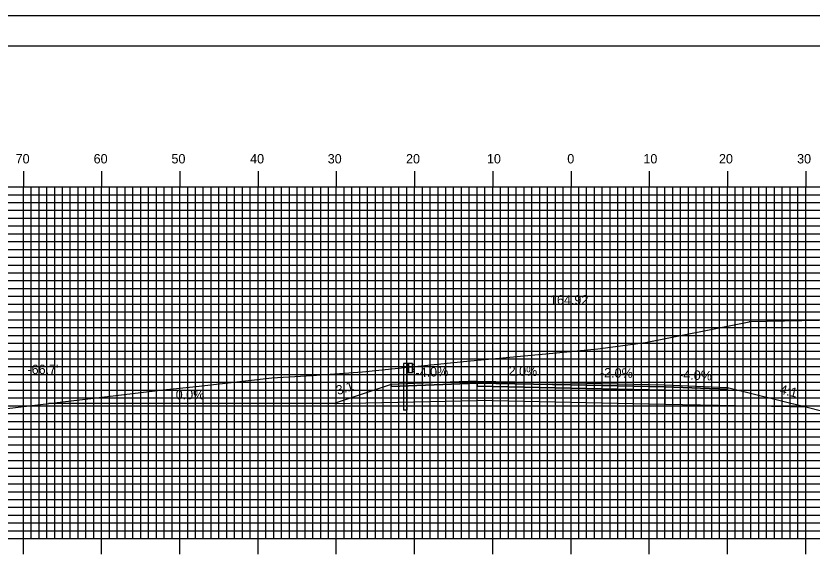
# Model space of a CAD drawing. Extents: x 1793666 to 1794009, y 442591 to 442811.
# Drawn here: x 1793760.4 to 1793862.1, y 442741.2 to 442810.5 of the extents above; entities that cross this region are included whole.
import ezdxf

# ---------------------------------------------------------------- set-up
doc = ezdxf.new("R2010")
doc.units = 0
for name, color, linetype in [('ANNOTATION', 7, 'Continuous'), ('BORDER', 7, 'Continuous'), ('D_Guardrail_Beam_Lt', 7, 'Continuous'), ('D_Roadway_Centerline', 7, 'Continuous'), ('D_Roadway_Centerline_Text', 7, 'Continuous'), ('D_Roadway_Edge_Shoulder', 7, 'Continuous'), ('D_Roadway_Edge_TW', 7, 'Continuous'), ('D_Roadway_FinishedGrade', 7, 'Continuous'), ('D_Roadway_Pavement', 7, 'Continuous'), ('D_Roadway_SlopeLines', 7, 'Continuous'), ('D_Roadway_SubGrade', 7, 'Continuous'), ('D_Text_Standard', 7, 'Continuous'), ('H_V ANNOTATION', 7, 'Continuous'), ('MAJOR', 7, 'Continuous'), ('MINOR', 7, 'Continuous'), ('PLOT BOUNDARY', 7, 'Continuous'), ('S_Roadway_Centerline', 7, 'Continuous')]:
    doc.layers.add(name, color=color, linetype=linetype)

msp = doc.modelspace()

# ---------------------------------------------------------------- linework, layer by layer
at = {"layer": 'BORDER'}
msp.add_lwpolyline([(1793681.71, 442596.67), (1794001.71, 442596.67), (1794001.71, 442806.67), (1793681.71, 442806.67)], close=True, dxfattribs=at)
at = {"layer": 'D_Guardrail_Beam_Lt'}
for p, q in [((1793809.88, 442766.09), (1793809.88, 442760.09)), ((1793810.36, 442766.09), (1793809.88, 442766.09)), ((1793811.04, 442766.09), (1793810.36, 442766.09)), ((1793810.36, 442766.09), (1793810.36, 442764.92)), ((1793810.42, 442766.09), (1793810.42, 442764.92)), ((1793810.52, 442766.09), (1793810.52, 442764.92)), ((1793811.04, 442764.92), (1793811.04, 442766.09)), ((1793811.04, 442766), (1793811.12, 442765.99)), ((1793811.13, 442765.98), (1793811.28, 442765.88)), ((1793810.36, 442764.92), (1793811.04, 442764.92)), ((1793810.38, 442760.09), (1793810.38, 442764.92)), ((1793811.12, 442765.02), (1793811.04, 442765)), ((1793811.05, 442765.54), (1793811.05, 442765.47)), ((1793811.28, 442765.74), (1793811.08, 442765.6)), ((1793811.08, 442765.4), (1793811.28, 442765.27)), ((1793811.28, 442765.12), (1793811.13, 442765.02)), ((1793810.38, 442760.09), (1793809.88, 442760.09))]:
    msp.add_line(p, q, dxfattribs=at)
for centre, major_axis, start_param, end_param in [((1793811.11, 442765.95), (0.0417, 0), 0.959931, 1.376053), ((1793811.13, 442765.54), (-0.0789, 0), 5.323254, 6.283185), ((1793811.13, 442765.47), (-0.0789, 0), 6.283185, 7.243116), ((1793811.11, 442765.06), (0.0417, 0), 4.907132, 5.323254), ((1793811.23, 442765.81), (0.0877, 0), 5.323254, 7.243116), ((1793811.23, 442765.2), (0.0877, 0), 5.323254, 7.243116)]:
    msp.add_ellipse(centre, major_axis=major_axis, ratio=0.995501, start_param=start_param, end_param=end_param, dxfattribs=at)
at = {"layer": 'D_Roadway_Edge_Shoulder'}
for points in [[(1793819.31, 442763.82), (1793811.31, 442763.5), (1793811.31, 442763.5), (1793808.31, 442763.38), (1793808.31, 442763.13), (1793819.31, 442763.57)], [(1793843.31, 442763.34), (1793851.31, 442763.02), (1793851.31, 442762.77), (1793843.31, 442763.09)]]:
    msp.add_lwpolyline(points, close=True, dxfattribs=at)
at = {"layer": 'D_Roadway_Edge_TW'}
msp.add_lwpolyline([(1793819.31, 442763.57), (1793819.31, 442763.82), (1793831.31, 442763.58), (1793843.31, 442763.34), (1793843.31, 442763.09), (1793831.31, 442763.33)], close=True, dxfattribs=at)
at = {"layer": 'D_Roadway_FinishedGrade'}
msp.add_line((1793801.04, 442760.96), (1793764.5, 442760.96), dxfattribs=at)
at = {"layer": 'D_Roadway_Pavement'}
for points in [[(1793819.31, 442763.57), (1793819.31, 442763.16)], [(1793819.31, 442763.57), (1793819.31, 442763.16)], [(1793843.31, 442763.09), (1793843.31, 442762.68)]]:
    msp.add_lwpolyline(points, dxfattribs=at)
msp.add_lwpolyline([(1793819.31, 442763.16), (1793819.31, 442763.57), (1793831.31, 442763.33), (1793843.31, 442763.09), (1793843.31, 442762.68), (1793831.31, 442762.92)], close=True, dxfattribs=at)
at = {"layer": 'D_Roadway_SlopeLines'}
msp.add_line((1793808.31, 442763.38), (1793801.04, 442760.96), dxfattribs=at)
msp.add_lwpolyline([(1793851.31, 442763.02), (1793861.32, 442760.52)], dxfattribs=at)
at = {"layer": 'D_Roadway_SubGrade'}
msp.add_line((1793861.49, 442760.48), (1793863.31, 442760.02), dxfattribs=at)
for points in [[(1793819.31, 442763.16), (1793819.31, 442763.57), (1793808.31, 442763.13), (1793808.31, 442763.38), (1793801.04, 442760.96), (1793819.31, 442761.32)], [(1793819.31, 442761.32), (1793819.31, 442763.57), (1793819.31, 442763.16), (1793831.31, 442762.92), (1793843.31, 442762.68), (1793843.31, 442763.09), (1793843.31, 442760.84), (1793831.31, 442761.08)], [(1793843.31, 442762.68), (1793843.31, 442763.09), (1793851.31, 442762.77), (1793851.31, 442763.02), (1793861.49, 442760.48), (1793843.31, 442760.84)]]:
    msp.add_lwpolyline(points, close=True, dxfattribs=at)
at = {"layer": 'MAJOR'}
for p, q in [((1793761.31, 442790.67), (1793761.31, 442788.67)), ((1793771.31, 442790.67), (1793771.31, 442788.67)), ((1793781.31, 442790.67), (1793781.31, 442788.67)), ((1793791.31, 442790.67), (1793791.31, 442788.67)), ((1793801.31, 442790.67), (1793801.31, 442788.67)), ((1793811.31, 442790.67), (1793811.31, 442788.67)), ((1793821.31, 442790.67), (1793821.31, 442788.67)), ((1793831.31, 442790.67), (1793831.31, 442788.67)), ((1793841.31, 442790.67), (1793841.31, 442788.67)), ((1793851.31, 442790.67), (1793851.31, 442788.67)), ((1793861.31, 442790.67), (1793861.31, 442788.67)), ((1793691.31, 442788.67), (1793971.31, 442788.67)), ((1793691.31, 442788.67), (1793971.31, 442788.67)), ((1793761.31, 442743.67), (1793761.31, 442788.67)), ((1793771.31, 442743.67), (1793771.31, 442788.67)), ((1793781.31, 442743.67), (1793781.31, 442788.67)), ((1793791.31, 442743.67), (1793791.31, 442788.67)), ((1793801.31, 442743.67), (1793801.31, 442788.67)), ((1793811.31, 442743.67), (1793811.31, 442788.67)), ((1793821.31, 442743.67), (1793821.31, 442788.67)), ((1793831.31, 442743.67), (1793831.31, 442788.67)), ((1793841.31, 442743.67), (1793841.31, 442788.67)), ((1793851.31, 442743.67), (1793851.31, 442788.67)), ((1793861.31, 442743.67), (1793861.31, 442788.67)), ((1793691.31, 442783.67), (1793971.31, 442783.67)), ((1793691.31, 442778.67), (1793971.31, 442778.67)), ((1793691.31, 442773.67), (1793971.31, 442773.67)), ((1793691.31, 442768.67), (1793971.31, 442768.67)), ((1793691.31, 442763.67), (1793971.31, 442763.67)), ((1793691.31, 442758.67), (1793971.31, 442758.67)), ((1793691.31, 442753.67), (1793971.31, 442753.67)), ((1793691.31, 442748.67), (1793971.31, 442748.67)), ((1793691.31, 442743.67), (1793971.31, 442743.67)), ((1793691.31, 442743.67), (1793971.31, 442743.67)), ((1793761.31, 442741.66), (1793761.31, 442743.67)), ((1793771.31, 442741.66), (1793771.31, 442743.67)), ((1793781.31, 442741.66), (1793781.31, 442743.67)), ((1793791.31, 442741.66), (1793791.31, 442743.67)), ((1793801.31, 442741.66), (1793801.31, 442743.67)), ((1793811.31, 442741.66), (1793811.31, 442743.67)), ((1793821.31, 442741.66), (1793821.31, 442743.67)), ((1793831.31, 442741.66), (1793831.31, 442743.67)), ((1793841.31, 442741.66), (1793841.31, 442743.67)), ((1793851.31, 442741.66), (1793851.31, 442743.67)), ((1793861.31, 442741.66), (1793861.31, 442743.67))]:
    msp.add_line(p, q, dxfattribs=at)
at = {"layer": 'MINOR'}
for p, q in [((1793762.31, 442743.67), (1793762.31, 442788.67)), ((1793763.31, 442743.67), (1793763.31, 442788.67)), ((1793764.31, 442743.67), (1793764.31, 442788.67)), ((1793765.31, 442743.67), (1793765.31, 442788.67)), ((1793766.31, 442743.67), (1793766.31, 442788.67)), ((1793767.31, 442743.67), (1793767.31, 442788.67)), ((1793768.31, 442743.67), (1793768.31, 442788.67)), ((1793769.31, 442743.67), (1793769.31, 442788.67)), ((1793770.31, 442743.67), (1793770.31, 442788.67)), ((1793772.31, 442743.67), (1793772.31, 442788.67)), ((1793773.31, 442743.67), (1793773.31, 442788.67)), ((1793774.31, 442743.67), (1793774.31, 442788.67)), ((1793775.31, 442743.67), (1793775.31, 442788.67)), ((1793776.31, 442743.67), (1793776.31, 442788.67)), ((1793777.31, 442743.67), (1793777.31, 442788.67)), ((1793778.31, 442743.67), (1793778.31, 442788.67)), ((1793779.31, 442743.67), (1793779.31, 442788.67)), ((1793780.31, 442743.67), (1793780.31, 442788.67)), ((1793782.31, 442743.67), (1793782.31, 442788.67)), ((1793783.31, 442743.67), (1793783.31, 442788.67)), ((1793784.31, 442743.67), (1793784.31, 442788.67)), ((1793785.31, 442743.67), (1793785.31, 442788.67)), ((1793786.31, 442743.67), (1793786.31, 442788.67)), ((1793787.31, 442743.67), (1793787.31, 442788.67)), ((1793788.31, 442743.67), (1793788.31, 442788.67)), ((1793789.31, 442743.67), (1793789.31, 442788.67)), ((1793790.31, 442743.67), (1793790.31, 442788.67)), ((1793792.31, 442743.67), (1793792.31, 442788.67)), ((1793793.31, 442743.67), (1793793.31, 442788.67)), ((1793794.31, 442743.67), (1793794.31, 442788.67)), ((1793795.31, 442743.67), (1793795.31, 442788.67)), ((1793796.31, 442743.67), (1793796.31, 442788.67)), ((1793797.31, 442743.67), (1793797.31, 442788.67)), ((1793798.31, 442743.67), (1793798.31, 442788.67)), ((1793799.31, 442743.67), (1793799.31, 442788.67)), ((1793800.31, 442743.67), (1793800.31, 442788.67)), ((1793802.31, 442743.67), (1793802.31, 442788.67)), ((1793803.31, 442743.67), (1793803.31, 442788.67)), ((1793804.31, 442743.67), (1793804.31, 442788.67)), ((1793805.31, 442743.67), (1793805.31, 442788.67)), ((1793806.31, 442743.67), (1793806.31, 442788.67)), ((1793807.31, 442743.67), (1793807.31, 442788.67)), ((1793808.31, 442743.67), (1793808.31, 442788.67)), ((1793809.31, 442743.67), (1793809.31, 442788.67)), ((1793810.31, 442743.67), (1793810.31, 442788.67)), ((1793812.31, 442743.67), (1793812.31, 442788.67)), ((1793813.31, 442743.67), (1793813.31, 442788.67)), ((1793814.31, 442743.67), (1793814.31, 442788.67)), ((1793815.31, 442743.67), (1793815.31, 442788.67)), ((1793816.31, 442743.67), (1793816.31, 442788.67)), ((1793817.31, 442743.67), (1793817.31, 442788.67)), ((1793818.31, 442743.67), (1793818.31, 442788.67)), ((1793819.31, 442743.67), (1793819.31, 442788.67)), ((1793820.31, 442743.67), (1793820.31, 442788.67)), ((1793822.31, 442743.67), (1793822.31, 442788.67)), ((1793823.31, 442743.67), (1793823.31, 442788.67)), ((1793824.31, 442743.67), (1793824.31, 442788.67)), ((1793825.31, 442743.67), (1793825.31, 442788.67)), ((1793826.31, 442743.67), (1793826.31, 442788.67)), ((1793827.31, 442743.67), (1793827.31, 442788.67)), ((1793828.31, 442743.67), (1793828.31, 442788.67)), ((1793829.31, 442743.67), (1793829.31, 442788.67)), ((1793830.31, 442743.67), (1793830.31, 442788.67)), ((1793832.31, 442743.67), (1793832.31, 442788.67)), ((1793833.31, 442743.67), (1793833.31, 442788.67)), ((1793834.31, 442743.67), (1793834.31, 442788.67)), ((1793835.31, 442743.67), (1793835.31, 442788.67)), ((1793836.31, 442743.67), (1793836.31, 442788.67)), ((1793837.31, 442743.67), (1793837.31, 442788.67)), ((1793838.31, 442743.67), (1793838.31, 442788.67)), ((1793839.31, 442743.67), (1793839.31, 442788.67)), ((1793840.31, 442743.67), (1793840.31, 442788.67)), ((1793842.31, 442743.67), (1793842.31, 442788.67)), ((1793843.31, 442743.67), (1793843.31, 442788.67)), ((1793844.31, 442743.67), (1793844.31, 442788.67)), ((1793845.31, 442743.67), (1793845.31, 442788.67)), ((1793846.31, 442743.67), (1793846.31, 442788.67)), ((1793847.31, 442743.67), (1793847.31, 442788.67)), ((1793848.31, 442743.67), (1793848.31, 442788.67)), ((1793849.31, 442743.67), (1793849.31, 442788.67)), ((1793850.31, 442743.67), (1793850.31, 442788.67)), ((1793852.31, 442743.67), (1793852.31, 442788.67)), ((1793853.31, 442743.67), (1793853.31, 442788.67)), ((1793854.31, 442743.67), (1793854.31, 442788.67)), ((1793855.31, 442743.67), (1793855.31, 442788.67)), ((1793856.31, 442743.67), (1793856.31, 442788.67)), ((1793857.31, 442743.67), (1793857.31, 442788.67)), ((1793858.31, 442743.67), (1793858.31, 442788.67)), ((1793859.31, 442743.67), (1793859.31, 442788.67)), ((1793860.31, 442743.67), (1793860.31, 442788.67)), ((1793691.31, 442787.67), (1793971.31, 442787.67)), ((1793691.31, 442786.67), (1793971.31, 442786.67)), ((1793691.31, 442785.67), (1793971.31, 442785.67)), ((1793691.31, 442784.67), (1793971.31, 442784.67)), ((1793691.31, 442782.67), (1793971.31, 442782.67)), ((1793691.31, 442781.67), (1793971.31, 442781.67)), ((1793691.31, 442780.67), (1793971.31, 442780.67)), ((1793691.31, 442779.67), (1793971.31, 442779.67)), ((1793691.31, 442777.67), (1793971.31, 442777.67)), ((1793691.31, 442776.67), (1793971.31, 442776.67)), ((1793691.31, 442775.67), (1793971.31, 442775.67)), ((1793691.31, 442774.67), (1793971.31, 442774.67)), ((1793691.31, 442772.67), (1793971.31, 442772.67)), ((1793691.31, 442771.67), (1793971.31, 442771.67)), ((1793691.31, 442770.67), (1793971.31, 442770.67)), ((1793691.31, 442769.67), (1793971.31, 442769.67)), ((1793691.31, 442767.67), (1793971.31, 442767.67)), ((1793691.31, 442766.67), (1793971.31, 442766.67)), ((1793691.31, 442765.67), (1793971.31, 442765.67)), ((1793691.31, 442764.67), (1793971.31, 442764.67)), ((1793691.31, 442762.67), (1793971.31, 442762.67)), ((1793691.31, 442761.67), (1793971.31, 442761.67)), ((1793691.31, 442760.67), (1793971.31, 442760.67)), ((1793691.31, 442759.67), (1793971.31, 442759.67)), ((1793691.31, 442757.67), (1793971.31, 442757.67)), ((1793691.31, 442756.67), (1793971.31, 442756.67)), ((1793691.31, 442755.67), (1793971.31, 442755.67)), ((1793691.31, 442754.67), (1793971.31, 442754.67)), ((1793691.31, 442752.67), (1793971.31, 442752.67)), ((1793691.31, 442751.67), (1793971.31, 442751.67)), ((1793691.31, 442750.67), (1793971.31, 442750.67)), ((1793691.31, 442749.67), (1793971.31, 442749.67)), ((1793691.31, 442747.67), (1793971.31, 442747.67)), ((1793691.31, 442746.67), (1793971.31, 442746.67)), ((1793691.31, 442745.67), (1793971.31, 442745.67)), ((1793691.31, 442744.67), (1793971.31, 442744.67))]:
    msp.add_line(p, q, dxfattribs=at)
at = {"layer": 'PLOT BOUNDARY'}
msp.add_lwpolyline([(1793665.53, 442590.55), (1794005.53, 442590.55), (1794005.53, 442810.55), (1793665.53, 442810.55)], close=True, dxfattribs=at)
at = {"layer": 'S_Roadway_Centerline'}
msp.add_lwpolyline([(1793757.39, 442760.1), (1793779.16, 442762.72), (1793783.39, 442763.12), (1793793.07, 442764.23), (1793798.2, 442764.52), (1793804.64, 442765), (1793818.01, 442766.36), (1793829.44, 442767.45), (1793834.74, 442767.93), (1793840.83, 442768.76), (1793854.1, 442771.42), (1793854.12, 442771.43), (1793854.14, 442771.43), (1793854.18, 442771.43), (1793871.9, 442771.77)], dxfattribs=at)

# ---------------------------------------------------------------- texts
at = {"layer": 'ANNOTATION'}
for s, rotation, p in [('-4.0%', 2.2906, (1793811.45, 442764.31)), ('2.0%', 358.8542, (1793823.32, 442764.54)), ('-2.0%', 358.8542, (1793835, 442764.31)), ('-4.0%', 357.7094, (1793845.11, 442764.07)), ('3:1', 18.4349, (1793801.51, 442762.02)), ('4:1', 345.9638, (1793857.91, 442762.24)), ('0.0%', 360, (1793780.78, 442761.49))]:
    msp.add_text(s, height=1.2, rotation=rotation, dxfattribs=at).set_placement(p)
at = {"layer": 'D_Roadway_Centerline'}
for s in ['C', 'L']:
    msp.add_text(s, height=0.0146, dxfattribs=at).set_placement((1793831.31, 442763.58))
at = {"layer": 'D_Roadway_Centerline_Text'}
msp.add_text('164.92', height=1.2, dxfattribs=at).set_placement((1793828.62, 442773.61))
at = {"layer": 'D_Text_Standard'}
msp.add_text("-66.7'", height=1.2, dxfattribs=at).set_placement((1793761.83, 442764.72))
at = {"layer": 'H_V ANNOTATION'}
for s, p in [('70', (1793760.32, 442791.67)), ('60', (1793770.29, 442791.67)), ('50', (1793780.24, 442791.67)), ('40', (1793790.29, 442791.67)), ('30', (1793800.21, 442791.67)), ('20', (1793810.22, 442791.67)), ('10', (1793820.56, 442791.67)), ('0', (1793830.83, 442791.67)), ('10', (1793840.56, 442791.67)), ('20', (1793850.22, 442791.67)), ('30', (1793860.21, 442791.67))]:
    msp.add_text(s, height=1.2, dxfattribs=at).set_placement(p)

doc.saveas('drawing.dxf')
